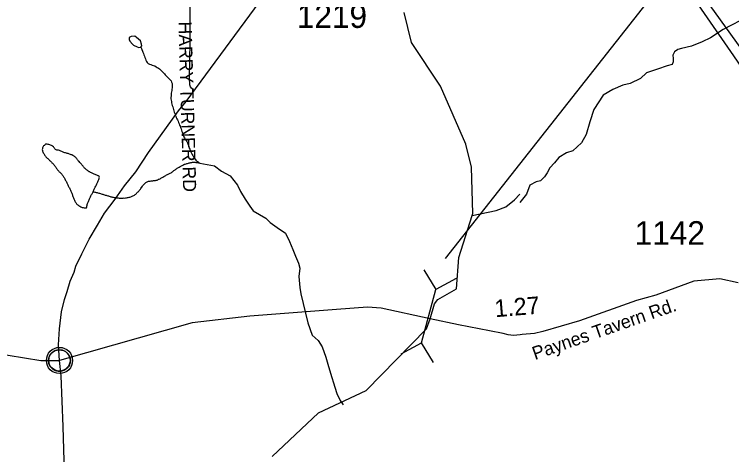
# Model space of a CAD drawing. Extents: x 1950930 to 2061844, y 904556 to 1017002.
# Drawn here: x 1996439 to 2001603, y 942619 to 945791 of the extents above; entities that cross this region are included whole.
import ezdxf

# ---------------------------------------------------------------- set-up
doc = ezdxf.new("R2010")
doc.units = 0
for name, color, linetype in [('Exist Civil Demographics Community CELL', 7, 'Continuous'), ('Exist Hydrographic Creek Single Shore', 7, 'Continuous'), ('Exist Hydrographic Misc Water Feature', 7, 'Continuous'), ('Exist Road Non-System Type 51', 7, 'Continuous'), ('Exist Road Non-System Type 51 Label', 7, 'Continuous'), ('Exist Road Primary NC Attributed', 7, 'Continuous'), ('Exist Road Primary US Structure Standard Bridge CELL', 7, 'Continuous'), ('Exist Road Secondary Structure Pipe CELL', 7, 'Continuous'), ('Exist Road Secondary Structure Pipe Number Label', 7, 'Continuous'), ('Exist Road Secondary Type 51 Attributed', 7, 'Continuous'), ('Exist Road Secondary Type 51 Label', 7, 'Continuous'), ('Exist Road Secondary Type 51 Number Label', 7, 'Continuous'), ('Exist Utilities Electrical Transmission Line', 7, 'Continuous')]:
    doc.layers.add(name, color=color, linetype=linetype)

msp = doc.modelspace()

# ---------------------------------------------------------------- linework, layer by layer
at = {"layer": 'Exist Civil Demographics Community CELL'}
msp.add_lwpolyline([(1996686.4, 943309.5), (1996687.4, 943315.1), (1996689.1, 943321.6), (1996692.1, 943328.8), (1996695, 943334.6), (1996698.3, 943340.3), (1996702.1, 943345.4), (1996706, 943349.8), (1996710.6, 943354.4), (1996716.2, 943359), (1996721.6, 943362.7), (1996726.5, 943365.5), (1996731.5, 943368), (1996737, 943370.3), (1996742.6, 943372.1), (1996746.9, 943373.3), (1996751.8, 943374), (1996755.9, 943374.7), (1996762.3, 943375), (1996766.7, 943374.9), (1996772.4, 943374.6), (1996777.3, 943373.9), (1996782.2, 943372.9), (1996787.2, 943371.5), (1996792.4, 943369.5), (1996799, 943366.6), (1996805.3, 943363.1), (1996810.3, 943359.6), (1996815.5, 943355.6), (1996818.8, 943352.4), (1996822.9, 943348), (1996826.8, 943343.4), (1996829.9, 943338.8), (1996833, 943333.8), (1996835.5, 943328.6), (1996837.5, 943323.6), (1996839.1, 943318.6), (1996840.3, 943314), (1996841.4, 943307.9), (1996842.1, 943303.2), (1996842.3, 943297.2), (1996842.1, 943291.4), (1996841.6, 943285.7), (1996840.6, 943280.3), (1996839, 943274.1), (1996837.1, 943268.3), (1996834.8, 943263.2), (1996831.7, 943257.2), (1996828.4, 943251.9), (1996824.9, 943247.2), (1996820.7, 943242.4), (1996815.4, 943237.5), (1996810.4, 943233.4), (1996805.4, 943229.9), (1996801.1, 943227.4), (1996794.2, 943224.2), (1996787.1, 943221.5), (1996781.1, 943220), (1996774.5, 943218.7), (1996770.1, 943218.2), (1996765.6, 943218), (1996760, 943218), (1996755.8, 943218.4), (1996750.1, 943219.1), (1996744.2, 943220.4), (1996739.6, 943221.7), (1996734.4, 943223.6), (1996729.9, 943225.6), (1996725.9, 943227.8), (1996719.1, 943231.9), (1996713.6, 943236.2), (1996708.6, 943240.7), (1996704.2, 943245.5), (1996701, 943249.5), (1996698, 943253.7), (1996693.9, 943260.8), (1996692.2, 943264.3), (1996690.5, 943268.3), (1996687.9, 943276.5), (1996686.4, 943283.6), (1996685.7, 943288.7), (1996685.3, 943295), (1996685.3, 943299.7), (1996685.8, 943306.2)], close=True, dxfattribs=at)
for centre, radius in [((1996764, 943297.1), 94.3), ((1996763.7, 943297.3), 76.7)]:
    msp.add_circle(centre, radius, dxfattribs=at)
at = {"layer": 'Exist Hydrographic Creek Single Shore'}
for points in [[(1999734.8, 944342.2), (1999738.9, 944354.9), (1999730.9, 944689.8), (1999689.9, 944854.8), (1999505.8, 945272), (1999297.9, 945588.2), (1999246.4, 945804.4)], [(1997350.2, 945554.4), (1997353.7, 945545.3), (1997357.4, 945536.3), (1997360.7, 945526.4), (1997364.4, 945517.3), (1997367.8, 945508.3), (1997371.3, 945498.4), (1997375.4, 945489.3), (1997378.9, 945480.2), (1997382.8, 945470.2), (1997386.3, 945460), (1997390.4, 945451.3), (1997395.7, 945442.8), (1997402.7, 945436.8), (1997411.5, 945432.6), (1997421, 945429.1), (1997430.6, 945425.6), (1997440.6, 945422.2), (1997449.9, 945418.7), (1997458.9, 945413.6), (1997467.3, 945408.3), (1997475.9, 945403.4), (1997483.7, 945397.8), (1997492.1, 945391.6), (1997499.5, 945384.7), (1997506.3, 945377.3), (1997512.6, 945369.8), (1997519.2, 945362.3), (1997525.9, 945354.8), (1997532.7, 945347.2), (1997539.1, 945339.8), (1997546.4, 945333), (1997553.8, 945325.4), (1997561.2, 945319), (1997567.2, 945311.2), (1997571.1, 945302.1), (1997574.1, 945292.3), (1997575.6, 945282.3), (1997576, 945272.5), (1997575.2, 945262.1), (1997573.9, 945252.2), (1997572.3, 945242.2), (1997570, 945232.4), (1997568.8, 945222.4), (1997567.8, 945212.9), (1997567, 945202.9), (1997566.3, 945192.4), (1997566.5, 945182.7), (1997567.8, 945172.7), (1997569.6, 945162.7), (1997571.3, 945152.6), (1997573.9, 945143), (1997576.2, 945133.6), (1997578.8, 945123.9), (1997581.5, 945114.2), (1997584, 945104), (1997586.8, 945095.1), (1997589.7, 945085.4), (1997593.4, 945075.8), (1997596.9, 945066.8), (1997600.4, 945057), (1997604.5, 945047.8), (1997608.4, 945038.7), (1997613.3, 945029.8), (1997617.2, 945020.7), (1997621.3, 945011.5), (1997625.4, 945002.4), (1997628.9, 944993.3), (1997632.6, 944984.3), (1997635.9, 944974.4), (1997639.1, 944965), (1997642, 944955.3), (1997645.3, 944946.2), (1997648.4, 944936.4), (1997651.4, 944927), (1997654.9, 944917.9), (1997658.8, 944908), (1997663.5, 944900), (1997668.9, 944891.5), (1997674.6, 944883.3), (1997680.1, 944874.8), (1997684.7, 944866), (1997688.5, 944856.8), (1997692, 944846.6), (1997695.1, 944837.6), (1997698.2, 944827.7), (1997701.7, 944818.7), (1997705.4, 944809.7), (1997709.7, 944800.4), (1997714.2, 944791.2), (1997718.7, 944782.1), (1997723.6, 944774), (1997728.9, 944764.7), (1997734.3, 944756.6), (1997739.6, 944747.9), (1997746.2, 944740.6), (1997753.6, 944733.7), (1997761.3, 944727.2), (1997770.4, 944720.6)], [(1997540.5, 944635.8), (1997546, 944639.1), (1997551.2, 944641.5), (1997556.7, 944644.3), (1997561.8, 944646.8), (1997567, 944650), (1997571.9, 944653.4), (1997576.6, 944657.1), (1997581.5, 944660.4), (1997586.4, 944664.6), (1997591.1, 944667.5), (1997596.1, 944671.6), (1997601, 944674.9), (1997606.1, 944677.8), (1997611, 944681.9), (1997616.2, 944684.4), (1997621.3, 944687.3), (1997626, 944690.6), (1997631.7, 944693.8), (1997636.9, 944697.1), (1997642, 944700.3), (1997647.1, 944702.4), (1997653.1, 944704.8), (1997658.2, 944708.1), (1997663.7, 944710.4), (1997669.5, 944712), (1997675, 944714), (1997680.8, 944715.5), (1997686.5, 944717.1), (1997692.2, 944718.6), (1997698.2, 944720.3), (1997704.3, 944721.7), (1997710.1, 944723.2), (1997716.2, 944724), (1997721.8, 944724.8), (1997727.9, 944725.4), (1997733.9, 944725.4), (1997739.8, 944725.3), (1997746, 944724.3), (1997751.7, 944723.4), (1997757.4, 944722.1), (1997763.8, 944721.2), (1997770.4, 944720.6)], [(1997770.4, 944720.6), (1997774.5, 944719.5), (1997880.7, 944698.5), (1997930.9, 944661.3), (1997992.8, 944627.2), (1998045.7, 944559.8), (1998067.9, 944514.3), (1998100.3, 944458.2), (1998134.7, 944408.3), (1998158.9, 944375), (1998249.4, 944323.1), (1998281.6, 944291.4), (1998331.6, 944255.8), (1998390.2, 944214.4), (1998418.7, 944153.3), (1998443.1, 944096.8), (1998463.4, 944049.1), (1998485.8, 943997.8), (1998494.2, 943961.2), (1998486.8, 943901.5), (1998495, 943823.5), (1998501.8, 943777.4), (1998553, 943567.9), (1998584.2, 943478.8), (1998626.3, 943440.6), (1998654.8, 943395.3), (1998681.2, 943321.5), (1998695.6, 943269.4), (1998714.2, 943205.3), (1998746.8, 943103.7), (1998761.2, 943059.8), (1998785.4, 943008.6), (1998806.5, 942977)], [(1997006.1, 944512.4), (1997011.9, 944511.2), (1997017.6, 944510.3), (1997022.9, 944509.5), (1997028.7, 944507.8), (1997034.4, 944506.6), (1997040.6, 944504.9), (1997046.5, 944503.1), (1997052.3, 944501.4), (1997058, 944499.7), (1997064, 944498), (1997070.1, 944496.2), (1997076.3, 944494.5), (1997081.8, 944492.5), (1997088, 944490.7), (1997093.5, 944489.1), (1997099.2, 944487.3), (1997105.4, 944485.7), (1997110.9, 944483.9), (1997117.1, 944482.2), (1997122.6, 944480.1), (1997128.3, 944478.5), (1997134.1, 944476.8), (1997139.6, 944475.1), (1997146, 944474.2), (1997151.5, 944472.6), (1997157.7, 944471.1), (1997163.2, 944470.3), (1997169.6, 944470.2), (1997175.3, 944469.3), (1997181, 944468.5), (1997187, 944468.4), (1997193.1, 944467.4), (1997199.1, 944467.3), (1997205.4, 944467.1), (1997211.4, 944467), (1997217.3, 944467), (1997223.3, 944466.9), (1997229.4, 944467.6), (1997235.4, 944467.5), (1997240.9, 944467.8), (1997247.5, 944468.9), (1997253.2, 944470.1), (1997259.2, 944470.7), (1997265.1, 944472.4), (1997271.3, 944473.8), (1997276.8, 944476.3), (1997282.5, 944477.8), (1997288.1, 944480.1), (1997293, 944482.7), (1997298.7, 944485.5), (1997303.5, 944488.8), (1997308.4, 944493), (1997312.7, 944495.9), (1997317.8, 944500.9), (1997321.9, 944505.1), (1997326.4, 944508.9), (1997330.5, 944513.1), (1997334.6, 944517.8), (1997338.7, 944521.6), (1997342.4, 944526.7), (1997346.3, 944531.4), (1997349.8, 944536.9), (1997353.5, 944542.1), (1997357, 944546.8), (1997360.7, 944551.9), (1997364.6, 944556.6), (1997368.3, 944561.3), (1997372.6, 944566.4), (1997376, 944570.3), (1997380.2, 944574.2), (1997385.1, 944578.3), (1997389.4, 944581.6), (1997394.5, 944583.7), (1997400, 944586.2), (1997405.8, 944587.7), (1997411.3, 944588.4), (1997417.7, 944590), (1997423.6, 944590.7), (1997429.8, 944591.4), (1997435.7, 944592.1), (1997441.9, 944592.7), (1997448.4, 944593.4), (1997454.4, 944594.1), (1997460.1, 944595.7), (1997466.1, 944597.2), (1997471.4, 944599.6), (1997476.9, 944602.1), (1997482.5, 944604.1), (1997488, 944606.5), (1997493.1, 944609.7), (1997498.5, 944613), (1997503.4, 944615.1), (1997508.9, 944618.3), (1997514.3, 944621.5), (1997519, 944624.9), (1997524.7, 944627.7), (1997529.6, 944630.1), (1997535.4, 944633.3), (1997540.5, 944635.8)], [(1998296, 942605.9), (1998629.8, 942920.6), (1998971.8, 943080.9), (1999406.1, 943526), (1999432.1, 943597.8), (1999464, 943704.2), (1999487.3, 943735.9), (1999621.9, 943812.5), (1999638.9, 944038.6), (1999734.8, 944342.2)]]:
    msp.add_lwpolyline(points, dxfattribs=at)
at = {"layer": 'Exist Hydrographic Misc Water Feature'}
for points in [[(2001726.4, 945776.8), (2001542.2, 945680.5), (2001450.4, 945620.7), (2001390.5, 945592.4), (2001314.3, 945560.5), (2001242.4, 945544.6), (2001214.4, 945536.3), (2001190.4, 945520.4), (2001178.4, 945496.3), (2001182.5, 945472.3), (2001182.4, 945448.3), (2001174.4, 945428.5), (2001138.5, 945420.4), (2001070.4, 945396.2), (2000990.4, 945368.3), (2000946.5, 945328.2), (2000872.6, 945292.3), (2000818.6, 945280.3), (2000746.7, 945248), (2000678.6, 945208), (2000610.8, 945104.1), (2000582.7, 945016.1), (2000554.9, 944924.1), (2000522.8, 944864), (2000459, 944807.9), (2000415, 944791.8), (2000358.9, 944759.8), (2000326.8, 944719.8), (2000294.9, 944683.7), (2000274.8, 944647.7), (2000254.9, 944619.8), (2000227.1, 944591.9), (2000195.1, 944583.7), (2000150.9, 944559.6), (2000127, 944495.8), (2000107.1, 944471.6), (2000079.1, 944435.8)], [(1997350.2, 945554.4), (1997356.2, 945564.9), (1997353.9, 945574.9), (1997347.5, 945600.7), (1997317.6, 945624.3), (1997305.3, 945632.6), (1997279.3, 945632.1), (1997265.7, 945624.4), (1997265.9, 945610.2), (1997270, 945596.2), (1997289.9, 945576.2), (1997297.9, 945568.1), (1997324.2, 945556.8), (1997336.3, 945552.5), (1997350.2, 945554.4)], [(1996655.1, 944846.7), (1996649.1, 944844.3), (1996645.9, 944839.6), (1996644.2, 944834.2), (1996642.4, 944828.3), (1996640.9, 944822.5), (1996639.9, 944816.9), (1996640.5, 944810.4), (1996642.2, 944804.4), (1996644.8, 944799.6), (1996647.3, 944793.9), (1996650.2, 944788.6), (1996653, 944782.9), (1996656.5, 944777.9), (1996659.4, 944773), (1996663.3, 944767.9), (1996666.8, 944763.7), (1996671.3, 944759.4), (1996675.6, 944755.5), (1996680.1, 944751.2), (1996684.4, 944746.8), (1996688.9, 944742.9), (1996693.2, 944738.6), (1996697.1, 944734.4), (1996701.6, 944730), (1996705.9, 944726.1), (1996710, 944721.9), (1996714.3, 944717.6), (1996718.2, 944713.3), (1996722.1, 944708.7), (1996726.2, 944704.4), (1996729.5, 944699.5), (1996733, 944694.4), (1996736.5, 944689.4), (1996739.4, 944684.2), (1996742.8, 944679.6), (1996746.3, 944674.1), (1996749.8, 944669.6), (1996754.1, 944665.2), (1996758, 944660.2), (1996762.3, 944655.9), (1996766.4, 944652.8), (1996771.4, 944648.4), (1996775.7, 944644.1), (1996780, 944639.8), (1996783.9, 944635.2), (1996787.3, 944630.6), (1996790.2, 944624.8), (1996793.3, 944620.3), (1996796.8, 944615), (1996799.2, 944610), (1996802.3, 944605.1), (1996805.2, 944599.5), (1996808.1, 944594.2), (1996810.9, 944588.4), (1996813.6, 944583.6), (1996816.5, 944577.9), (1996818.9, 944572.6), (1996821.8, 944566.9), (1996824.5, 944562.1), (1996826.9, 944556.3), (1996829.4, 944551.1), (1996831.8, 944545.5), (1996834.9, 944540.5), (1996837.2, 944534.5), (1996839.8, 944529.7), (1996842.3, 944524), (1996845.2, 944517.9), (1996847.2, 944513.1), (1996849.7, 944507.4), (1996851.7, 944501.5), (1996854.2, 944495.8), (1996856.7, 944489.8), (1996858.7, 944485), (1996860.8, 944479.3), (1996863.2, 944473.4), (1996865.7, 944467.6), (1996867.7, 944461.7), (1996870.2, 944456.9), (1996872.6, 944451.2), (1996875.1, 944445.9), (1996877.8, 944441.1), (1996880.6, 944435.3), (1996884.1, 944430.4), (1996887.2, 944426.2), (1996891.1, 944421.2), (1996895.6, 944417.7), (1996900.9, 944413.6), (1996906.3, 944410), (1996911.4, 944407.6), (1996916.9, 944405.1), (1996922.5, 944402.6), (1996928.2, 944399.8), (1996934.4, 944398), (1996940.9, 944397), (1996947.7, 944396), (1996952.8, 944396), (1996957.7, 944397.7), (1996960.4, 944401.7), (1996961.4, 944408.1)], [(1997006.1, 944512.4), (1997008.8, 944518.6), (1997011.1, 944524.7), (1997013.7, 944530.4), (1997016.4, 944535.7), (1997019.1, 944541.4), (1997021.9, 944546.2), (1997024.6, 944552.3), (1997026.8, 944557.7), (1997029.9, 944563.6), (1997032.6, 944568.9), (1997035, 944573.9), (1997037.3, 944579.6), (1997040, 944585.2), (1997042.2, 944591), (1997044.7, 944595.9), (1997046.9, 944601.6), (1997048.8, 944607.5), (1997050.4, 944612.1), (1997051.7, 944617.9), (1997048.4, 944623), (1997042.6, 944627.1), (1997037.5, 944629.8), (1997032, 944632.3), (1997026.4, 944634), (1997020.3, 944635.8), (1997014.7, 944638.7), (1997009.2, 944641.1), (1997004.1, 944643.5), (1996998.8, 944646.3), (1996993.2, 944648.8), (1996988.1, 944651.2), (1996982.8, 944654.9), (1996977.6, 944657.2), (1996972.1, 944660.5), (1996967.2, 944664.1), (1996962.3, 944667.3), (1996957.7, 944670.8), (1996953.2, 944674.7), (1996948.9, 944679), (1996945, 944683.4), (1996941.1, 944688.4), (1996936.6, 944692.7), (1996933.3, 944697.7), (1996929.2, 944701.9), (1996925.3, 944706.6), (1996921.4, 944710.8), (1996917.6, 944715.9), (1996913.7, 944720.2), (1996909.8, 944724.4), (1996905.9, 944729.4), (1996901.4, 944733.4), (1996898.1, 944738.3), (1996894, 944742.6), (1996890.3, 944747.6), (1996886.8, 944752.7), (1996882.9, 944756.9), (1996878.4, 944761.2), (1996874.1, 944765.2), (1996869.6, 944768.7), (1996864.4, 944771.8), (1996859.1, 944774.7), (1996853.6, 944778), (1996848, 944779.6), (1996842.5, 944782.1), (1996836.4, 944784.2), (1996830.8, 944786.7), (1996825.5, 944787.5), (1996819.3, 944789.3), (1996813.2, 944790.2), (1996808.1, 944792.2), (1996801.9, 944794), (1996796.2, 944795.6), (1996790.6, 944798.1), (1996785.1, 944800.5), (1996780.2, 944803.3), (1996774.6, 944805.8), (1996769.1, 944808.2), (1996763.4, 944810.4), (1996757.6, 944811.2), (1996751.5, 944812.1), (1996745.1, 944813.2), (1996739.4, 944814), (1996734.2, 944816.4), (1996730.3, 944821.5), (1996727.5, 944826.4), (1996723.6, 944831.4), (1996719.7, 944835.7), (1996714.8, 944840), (1996710.5, 944844), (1996705.3, 944846.8), (1996699.8, 944849.2), (1996693.6, 944851), (1996687.7, 944852.7), (1996681.7, 944853.7), (1996675.6, 944854.6), (1996670.1, 944855), (1996664.1, 944855.1), (1996659.6, 944850.9), (1996655.1, 944846.7)], [(1996961.4, 944408.1), (1996962.5, 944415.7), (1996964.1, 944421.1), (1996966.4, 944426.8), (1996968.4, 944431.8), (1996971.1, 944437.5), (1996973.3, 944443.2), (1996975.6, 944449), (1996977.8, 944454.7), (1996980.1, 944460.5), (1996982.6, 944465.4), (1996984.8, 944470.7), (1996987.3, 944476.4), (1996989.5, 944482.1), (1996992.6, 944486.9), (1996995.5, 944492.1), (1996999, 944497.8), (1997001.2, 944503.5), (1997006.1, 944512.4)], [(1999734.8, 944342.2), (1999907.1, 944377.4), (1999976.6, 944404.5), (2000039.3, 944455.5), (2000078.8, 944495.8)]]:
    msp.add_lwpolyline(points, dxfattribs=at)
at = {"layer": 'Exist Road Non-System Type 51'}
msp.add_lwpolyline([(1997729.2, 945246.8), (1997714.8, 945257.7), (1997706.6, 945267.2), (1997702.8, 945282.4), (1997700.9, 945331.8), (1997704.4, 945590.5), (1997705.2, 945782.9), (1997707.2, 945972.7)], dxfattribs=at)
at = {"layer": 'Exist Road Primary NC Attributed'}
for points in [[(1996764, 943297.1), (1996757.8, 943409.7), (1996764.2, 943525.6), (1996778.5, 943647.6), (1996800.6, 943737.5), (1996818.7, 943793.5), (1996841, 943867.4), (1996870.5, 943932.9), (1996881.1, 943977.3), (1996925.3, 944065.2), (1996977.5, 944171), (1997037.7, 944272.9), (1997088, 944358.6), (1997164.2, 944458.5), (1997230.9, 944554.5), (1997312.5, 944656.1), (1997404.9, 944795.8), (1997535.3, 944975.4), (1997621.6, 945095.2), (1997675.4, 945163.9), (1998310.1, 946025.3)], [(1996438, 941317), (1996475.7, 941391.5), (1996560.2, 941631.3), (1996589.1, 941712.9), (1996659.1, 941910.2), (1996746.3, 942154.1), (1996766.7, 942255.8), (1996781.7, 942343.1), (1996799.7, 942492.1), (1996790, 942822.6), (1996776.4, 943185.5), (1996764, 943297.1)]]:
    msp.add_lwpolyline(points, dxfattribs=at)
at = {"layer": 'Exist Road Secondary Structure Pipe CELL'}
for p, q in [((1999386.7, 943949.9), (1999473.7, 943807.9)), ((1999620.2, 943887), (1999473.7, 943807.9)), ((1999370.5, 943424.8), (1999473.7, 943807.9)), ((1999223.9, 943345.6), (1999370.5, 943424.8)), ((1999457.5, 943282.7), (1999370.5, 943424.8))]:
    msp.add_line(p, q, dxfattribs=at)
at = {"layer": 'Exist Road Secondary Structure Pipe Number Label'}
msp.add_line((1999543.9, 944032.2), (2001476.1, 946488.7), dxfattribs=at)
at = {"layer": 'Exist Road Secondary Type 51 Attributed'}
for points in [[(1993178, 943516.2), (1993545.8, 943748.2), (1993744.9, 943855), (1993851.7, 943908.4), (1993958.5, 943952.1), (1994065.3, 943966.7), (1994201.2, 943991), (1994308, 943991), (1994414.9, 943991), (1994681.9, 943908.4), (1995215.9, 943709.4), (1995414.9, 943641.4), (1995803.3, 943495.8), (1996084.9, 943403.5), (1996395.6, 943335.6), (1996628.6, 943296.7), (1996764, 943297.1)], [(2001650.2, 943857.1), (2001518.9, 943884.5), (2001330.1, 943868.7), (2001058.3, 943768.6), (2000918.2, 943728.7), (2000508.3, 943582.3), (2000243.6, 943504.7), (2000183.5, 943491.2), (2000094.8, 943483.8), (2000079.7, 943480.7), (2000032.5, 943476.8), (1999994.9, 943481.3), (1999957.3, 943490.3), (1999859.5, 943509.9), (1999635.4, 943553.6), (1999432.1, 943597.8), (1999079.5, 943674.8), (1998980.2, 943682.3), (1998759.1, 943664.2), (1998133.4, 943616.5), (1997718.1, 943567.9), (1996764, 943297.1)]]:
    msp.add_lwpolyline(points, dxfattribs=at)
at = {"layer": 'Exist Utilities Electrical Transmission Line'}
for points in [[(2000114, 947650.3), (2000456.3, 947148.5), (2001215, 946073), (2001594.2, 945522.7)], [(2000189.9, 947646.4), (2001074.8, 946372.7), (2001595.7, 945647.9)], [(2001595.7, 945647.9), (2002051.6, 945013.4), (2002450, 944426.1)], [(2001594.2, 945522.7), (2001971.6, 944975.2), (2002350.6, 944424.1)]]:
    msp.add_lwpolyline(points, dxfattribs=at)

# ---------------------------------------------------------------- texts
at = {"layer": 'Exist Road Non-System Type 51 Label'}
msp.add_text('  HARRY TURNER RD', height=95, rotation=271.5974, dxfattribs=at).set_placement((1997618.4, 945807.9))
at = {"layer": 'Exist Road Primary US Structure Standard Bridge CELL'}
msp.add_text('1.27', height=125, rotation=4.6724, dxfattribs=at).set_placement((1999900.8, 943608.5))
at = {"layer": 'Exist Road Secondary Type 51 Label'}
msp.add_text('Paynes Tavern Rd.', height=95, rotation=19.1923, dxfattribs=at).set_placement((2000186.9, 943300.1))
at = {"layer": 'Exist Road Secondary Type 51 Number Label'}
for s, p in [('1219', (1998472.5, 945692.8)), ('1142', (2000904.6, 944130.6))]:
    msp.add_text(s, height=170, dxfattribs=at).set_placement(p)

doc.saveas('drawing.dxf')
